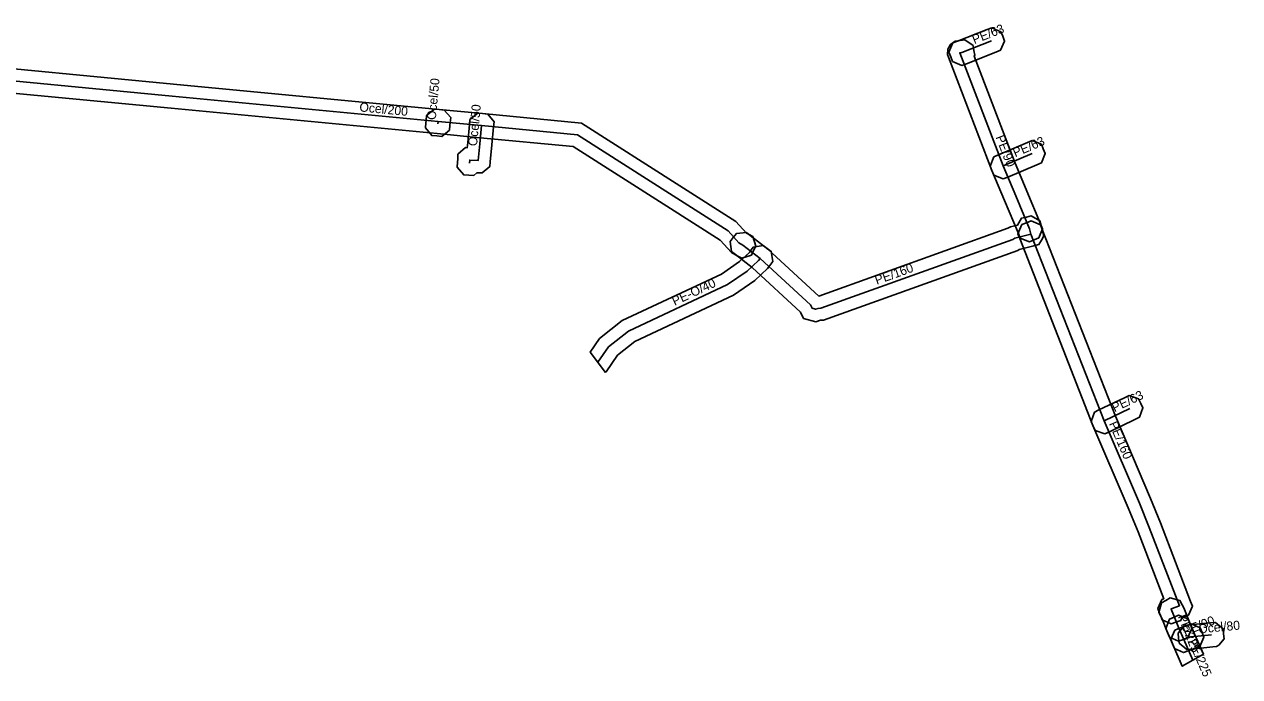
# Model space of a CAD drawing. Extents: x -444493 to -444287, y -1121040 to -1120972.
# Drawn here: x -444387.2 to -444286.8, y -1121039.7 to -1120985.8 of the extents above; entities that cross this region are included whole.
import ezdxf

# ---------------------------------------------------------------- set-up
doc = ezdxf.new("R2010")
doc.units = 0
for name, color, linetype in [('1', 7, 'Continuous'), ('14', 7, 'Continuous'), ('18', 7, 'Continuous'), ('20', 7, 'Continuous')]:
    doc.layers.add(name, color=color, linetype=linetype)

msp = doc.modelspace()

# ---------------------------------------------------------------- linework, layer by layer
at = {"layer": '1'}
for points in [[(-444310.48, -1120987.36), (-444310.1, -1120987.21), (-444307.66, -1120986.25), (-444307.27, -1120986.1), (-444306.51, -1120986.43), (-444306.36, -1120986.81), (-444306.21, -1120987.2), (-444306.54, -1120987.96), (-444306.92, -1120988.11), (-444309.36, -1120989.07), (-444309.75, -1120989.22), (-444310.51, -1120988.89), (-444310.66, -1120988.51), (-444310.81, -1120988.12)], [(-444308.68, -1120988.38), (-444308.73, -1120988.46), (-444305.4, -1120997.15), (-444304.37, -1120999.61), (-444303.23, -1121002.32), (-444303.07, -1121002.71), (-444303.38, -1121003.47), (-444303.76, -1121003.63), (-444304.15, -1121003.79), (-444304.91, -1121003.48), (-444305.07, -1121003.1), (-444306.21, -1121000.39), (-444307.26, -1120997.89), (-444310.84, -1120988.53), (-444310.92, -1120988.32), (-444310.89, -1120987.87), (-444310.78, -1120987.67), (-444310.67, -1120987.48), (-444310.3, -1120987.22), (-444310.07, -1120987.18), (-444309.89, -1120987.15), (-444309.49, -1120987.09), (-444308.81, -1120987.57), (-444308.74, -1120987.98)], [(-444354.08, -1120994.37), (-444354.04, -1120993.96), (-444354.02, -1120993.76), (-444353.98, -1120993.34), (-444353.34, -1120992.82), (-444352.93, -1120992.86), (-444352.52, -1120992.9), (-444351.99, -1120993.53), (-444352.03, -1120993.95), (-444352.05, -1120994.15), (-444352.09, -1120994.56), (-444352.73, -1120995.08), (-444353.14, -1120995.04), (-444353.55, -1120995.01)], [(-444350.77, -1120996.01), (-444350.62, -1120996.02), (-444350.58, -1120995.59), (-444350.44, -1120994.1), (-444350.4, -1120993.69), (-444349.76, -1120993.16), (-444349.35, -1120993.2), (-444348.93, -1120993.24), (-444348.41, -1120993.88), (-444348.45, -1120994.29), (-444348.59, -1120995.78), (-444348.72, -1120997.18), (-444348.76, -1120997.58), (-444349.38, -1120998.1), (-444349.78, -1120998.08), (-444349.82, -1120998.08), (-444350.08, -1120998.31), (-444350.5, -1120998.28), (-444350.91, -1120998.26), (-444351.46, -1120997.63), (-444351.43, -1120997.22), (-444351.41, -1120996.97), (-444351.39, -1120996.56)], [(-444307.1, -1120996.76), (-444306.72, -1120996.6), (-444304.32, -1120995.58), (-444303.94, -1120995.42), (-444303.17, -1120995.73), (-444303.01, -1120996.11), (-444302.85, -1120996.49), (-444303.16, -1120997.26), (-444303.54, -1120997.42), (-444305.94, -1120998.44), (-444306.32, -1120998.6), (-444307.09, -1120998.29), (-444307.25, -1120997.91), (-444307.41, -1120997.53)], [(-444325.77, -1121004.4), (-444321.56, -1121008.28), (-444305.93, -1121002.67), (-444305.73, -1121002.56), (-444305.13, -1121002.41), (-444304.81, -1121001.85), (-444304.41, -1121001.75), (-444304.01, -1121001.64), (-444303.29, -1121002.05), (-444303.18, -1121002.45), (-444303.07, -1121002.89), (-444302.96, -1121003.29), (-444303.16, -1121003.65), (-444303.37, -1121004.01), (-444303.78, -1121004.12), (-444304.99, -1121004.44), (-444305.12, -1121004.51), (-444321.18, -1121010.26), (-444321.41, -1121010.28), (-444321.81, -1121010.42), (-444322.82, -1121010.13), (-444323.07, -1121009.61), (-444327.07, -1121005.92), (-444328.45, -1121004.85), (-444328.78, -1121004.6), (-444328.88, -1121003.78), (-444328.63, -1121003.45), (-444328.38, -1121003.12), (-444327.55, -1121003.02), (-444327.23, -1121003.27)], [(-444293.2, -1121033.36), (-444293.05, -1121033.3), (-444295.18, -1121027.77), (-444295.98, -1121025.78), (-444298.91, -1121018.97), (-444304.96, -1121003.52), (-444305.11, -1121003.13), (-444304.78, -1121002.37), (-444304.4, -1121002.22), (-444304.01, -1121002.07), (-444303.25, -1121002.4), (-444303.1, -1121002.78), (-444297.05, -1121018.21), (-444294.14, -1121025.02), (-444293.32, -1121027.03), (-444290.83, -1121033.51), (-444290.68, -1121033.9), (-444291.01, -1121034.65), (-444291.4, -1121034.8), (-444291.55, -1121034.86), (-444291.65, -1121035.09), (-444292.04, -1121035.24), (-444292.43, -1121035.38), (-444293.18, -1121035.04), (-444293.33, -1121034.65), (-444293.39, -1121034.49), (-444293.53, -1121034.11)], [(-444339.19, -1121014.59), (-444340.46, -1121012.91), (-444339.69, -1121011.79), (-444337.82, -1121010.31), (-444329.62, -1121006.46), (-444328.12, -1121005.43), (-444327.3, -1121004.67), (-444327.23, -1121004.57), (-444326.99, -1121004.24), (-444326.17, -1121004.11), (-444325.84, -1121004.35), (-444325.5, -1121004.59), (-444325.37, -1121005.41), (-444325.61, -1121005.75), (-444325.8, -1121006.01), (-444326.86, -1121006.99), (-444328.62, -1121008.2), (-444336.76, -1121012.03), (-444338.21, -1121013.17), (-444339.15, -1121014.53)], [(-444298.78, -1121017.86), (-444298.41, -1121017.69), (-444296.29, -1121016.68), (-444295.92, -1121016.5), (-444295.14, -1121016.78), (-444294.96, -1121017.15), (-444294.78, -1121017.52), (-444295.06, -1121018.3), (-444295.43, -1121018.48), (-444297.55, -1121019.49), (-444297.92, -1121019.67), (-444298.71, -1121019.39), (-444298.88, -1121019.02), (-444299.06, -1121018.65)], [(-444292.58, -1121036.48), (-444292.73, -1121036.09), (-444293.2, -1121034.91), (-444293.26, -1121034.79), (-444293.47, -1121034.42), (-444293.24, -1121033.63), (-444292.88, -1121033.43), (-444292.51, -1121033.23), (-444291.72, -1121033.45), (-444291.52, -1121033.81), (-444291.38, -1121034.05), (-444290.87, -1121035.36), (-444290.72, -1121035.75), (-444291.05, -1121036.51), (-444291.43, -1121036.66), (-444291.82, -1121036.81)], [(-444290.47, -1121036.27), (-444289.78, -1121037.87), (-444291.53, -1121038.88), (-444292.31, -1121037.07), (-444292.72, -1121036.13), (-444292.88, -1121035.75), (-444292.58, -1121034.98), (-444292.2, -1121034.81), (-444291.82, -1121034.65), (-444291.05, -1121034.95), (-444290.88, -1121035.33)], [(-444288.51, -1121037.14), (-444288.7, -1121037.25), (-444289, -1121037.28), (-444290.72, -1121037.45), (-444291.14, -1121037.49), (-444291.78, -1121036.96), (-444291.82, -1121036.55), (-444291.85, -1121036.13), (-444291.33, -1121035.5), (-444290.92, -1121035.46), (-444289.19, -1121035.29), (-444288.78, -1121035.25), (-444288.14, -1121035.77), (-444288.1, -1121036.19), (-444288.06, -1121036.6)], [(-444292.14, -1121035.89), (-444291.75, -1121035.74), (-444291.18, -1121035.52), (-444290.79, -1121035.37), (-444290.04, -1121035.7), (-444289.89, -1121036.09), (-444289.74, -1121036.48), (-444290.07, -1121037.23), (-444290.46, -1121037.38), (-444291.03, -1121037.6), (-444291.42, -1121037.75), (-444292.17, -1121037.42), (-444292.32, -1121037.03), (-444292.47, -1121036.64)]]:
    msp.add_lwpolyline(points, close=True, dxfattribs=at)
msp.add_lwpolyline([(-444394.42, -1120988.9), (-444374.91, -1120990.76), (-444352.93, -1120992.86), (-444349.35, -1120993.2), (-444341.19, -1120993.98), (-444333.06, -1120999.16), (-444328.41, -1121002.12), (-444327.55, -1121003.09), (-444327.38, -1121003.17), (-444327.01, -1121003.36), (-444326.76, -1121004.15), (-444326.95, -1121004.52), (-444327.14, -1121004.89), (-444327.93, -1121005.14), (-444328.3, -1121004.95), (-444328.79, -1121004.69), (-444329.72, -1121003.66), (-444334.13, -1121000.84), (-444341.86, -1120995.92), (-444349.54, -1120995.19), (-444353.12, -1120994.85), (-444375.1, -1120992.75), (-444394.6, -1120990.89)], dxfattribs=at)
at = {"layer": '14'}
for points in [[(-444304.15, -1121002.71), (-444305.29, -1121000), (-444306.33, -1120997.52), (-444309.91, -1120988.17), (-444309.73, -1120988.14)], [(-444309.73, -1120988.14), (-444307.29, -1120987.18)], [(-444394.51, -1120989.89), (-444375, -1120991.75), (-444353.03, -1120993.85), (-444349.44, -1120994.19), (-444341.52, -1120994.95), (-444333.6, -1121000), (-444329.06, -1121002.89), (-444328.17, -1121003.89), (-444327.84, -1121004.06)], [(-444353.04, -1120994.05), (-444353.03, -1120993.85)], [(-444306.33, -1120997.52), (-444303.93, -1120996.5)], [(-444304.15, -1121002.71), (-444304.03, -1121003.15), (-444305.36, -1121003.5), (-444305.53, -1121003.59), (-444321.4, -1121009.28), (-444321.62, -1121009.3), (-444321.83, -1121009.37), (-444322.11, -1121009.29), (-444322.25, -1121009), (-444326.42, -1121005.16), (-444327.84, -1121004.06)], [(-444304.03, -1121003.15), (-444297.98, -1121018.59), (-444295.06, -1121025.4), (-444294.25, -1121027.4), (-444291.76, -1121033.87), (-444292.45, -1121034.14), (-444292.39, -1121034.3)], [(-444326.42, -1121005.16), (-444326.55, -1121005.34), (-444327.49, -1121006.21), (-444329.12, -1121007.33), (-444337.29, -1121011.17), (-444338.95, -1121012.48), (-444339.82, -1121013.75)], [(-444297.98, -1121018.59), (-444295.86, -1121017.58)], [(-444291.8, -1121035.73), (-444292.29, -1121034.48), (-444292.39, -1121034.3)], [(-444290.65, -1121038.37), (-444291.39, -1121036.67), (-444291.8, -1121035.73)], [(-444290.82, -1121036.45), (-444289.1, -1121036.28)], [(-444291.39, -1121036.67), (-444290.82, -1121036.45)]]:
    msp.add_lwpolyline(points, dxfattribs=at)
at = {"layer": '18'}
msp.add_lwpolyline([(-444349.44, -1120994.19), (-444349.58, -1120995.69), (-444349.72, -1120997.08), (-444350.42, -1120997.04), (-444350.43, -1120997.28)], dxfattribs=at)

# ---------------------------------------------------------------- texts
at = {"layer": '20'}
for s, rotation, p in [('PE/63', 21.4768, (-444308.71, -1120987.46)), ('Ocel/50', 84.5461, (-444353.23, -1120993.75)), ('Ocel/200', 354.5464, (-444359.56, -1120993.01)), ('Ocel/50', 84.55, (-444349.82, -1120995.91)), ('PE/90', 290.9512, (-444306.96, -1120995.14)), ('PE/63', 23.0255, (-444305.33, -1120996.81)), ('PE/160', 19.7247, (-444316.77, -1121007.35)), ('PE-O/40', 25.1741, (-444333.48, -1121009.09)), ('PE/63', 25.4738, (-444297.12, -1121017.89)), ('PE/160', 293.2087, (-444297.6, -1121018.82)), ('PE/225', 291.4052, (-444291.9, -1121034.76)), ('PE/90', 21.1048, (-444291.3, -1121036.36)), ('Ocel/80', 5.536, (-444290.16, -1121036.17)), ('PE/225', 293.3535, (-444291.05, -1121036.81))]:
    msp.add_text(s, height=0.75, rotation=rotation, dxfattribs=at).set_placement(p)

doc.saveas('drawing.dxf')
